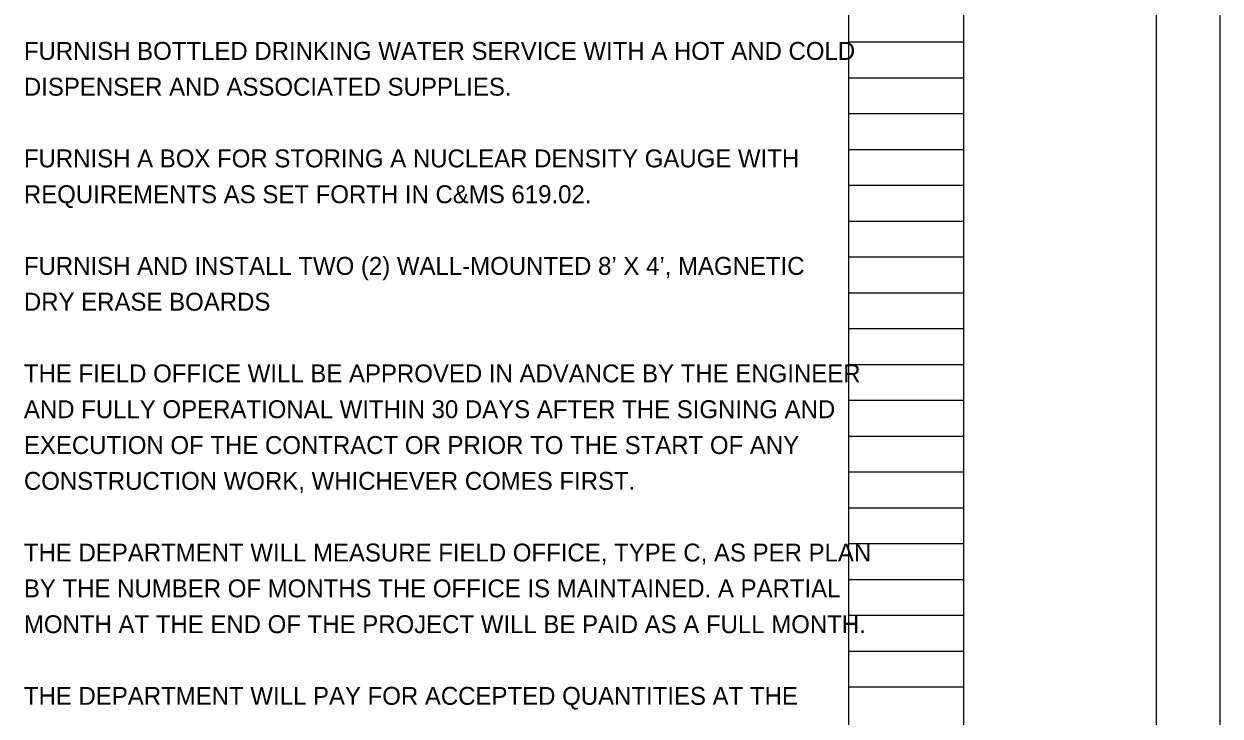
# Model space of a CAD drawing. Extents: x 0 to 74, y -27.6 to 51.8.
# Drawn here: x 24.66 to 34, y 5.51 to 10.92 of the extents above; entities that cross this region are included whole.
import ezdxf

# ---------------------------------------------------------------- set-up
doc = ezdxf.new("R2010")
doc.units = 0
for name, color, linetype in [('Level 1', 7, 'Continuous'), ('Level 2', 7, 'Continuous'), ('Level 3', 7, 'Continuous'), ('Level 4', 7, 'Continuous')]:
    doc.layers.add(name, color=color, linetype=linetype)

msp = doc.modelspace()

# ---------------------------------------------------------------- linework, layer by layer
at = {"layer": 'Level 1'}
msp.add_lwpolyline([(0, 0), (34, 0), (34, 22), (0, 22)], close=True, dxfattribs=at)
at = {"layer": 'Level 2'}
msp.add_line((32, 0.5), (32, 21.5), dxfattribs=at)
msp.add_lwpolyline([(1.5, 21.5), (33.5, 21.5), (33.5, 0.5), (1.5, 0.5)], close=True, dxfattribs=at)
at = {"layer": 'Level 3'}
for p, q in [((31.1, 0.98), (31.1, 21.14)), ((32, 0.98), (32, 21.14)), ((31.1, 10.78), (32, 10.78)), ((31.1, 10.5), (32, 10.5)), ((31.1, 10.22), (32, 10.22)), ((31.1, 9.94), (32, 9.94)), ((31.1, 9.66), (32, 9.66)), ((31.1, 9.38), (32, 9.38)), ((31.1, 9.1), (32, 9.1)), ((31.1, 8.82), (32, 8.82)), ((31.1, 8.54), (32, 8.54)), ((31.1, 8.26), (32, 8.26)), ((31.1, 7.98), (32, 7.98)), ((31.1, 7.7), (32, 7.7)), ((31.1, 7.42), (32, 7.42)), ((31.1, 7.14), (32, 7.14)), ((31.1, 6.86), (32, 6.86)), ((31.1, 6.58), (32, 6.58)), ((31.1, 6.3), (32, 6.3)), ((31.1, 6.02), (32, 6.02)), ((31.1, 5.74), (32, 5.74))]:
    msp.add_line(p, q, dxfattribs=at)

# ---------------------------------------------------------------- texts
at = {"layer": 'Level 4'}
for s, p in [('FURNISH BOTTLED DRINKING WATER SERVICE WITH A HOT AND COLD ', (24.66, 10.64)), ('DISPENSER AND ASSOCIATED SUPPLIES.', (24.66, 10.36)), ('FURNISH A BOX FOR STORING A NUCLEAR DENSITY GAUGE WITH ', (24.66, 9.8)), ('REQUIREMENTS AS SET FORTH IN C&MS 619.02.', (24.66, 9.52)), ('FURNISH AND INSTALL TWO (2) WALL-MOUNTED 8’ X 4’, MAGNETIC ', (24.66, 8.96)), ('DRY ERASE BOARDS', (24.66, 8.68)), ('THE FIELD OFFICE WILL BE APPROVED IN ADVANCE BY THE ENGINEER ', (24.66, 8.12)), ('AND FULLY OPERATIONAL WITHIN 30 DAYS AFTER THE SIGNING AND ', (24.66, 7.84)), ('EXECUTION OF THE CONTRACT OR PRIOR TO THE START OF ANY ', (24.66, 7.56)), ('CONSTRUCTION WORK, WHICHEVER COMES FIRST.', (24.66, 7.28)), ('THE DEPARTMENT WILL MEASURE FIELD OFFICE, TYPE C, AS PER PLAN ', (24.66, 6.72)), ('BY THE NUMBER OF MONTHS THE OFFICE IS MAINTAINED. A PARTIAL ', (24.66, 6.44)), ('MONTH AT THE END OF THE PROJECT WILL BE PAID AS A FULL MONTH.', (24.66, 6.16)), ('THE DEPARTMENT WILL PAY FOR ACCEPTED QUANTITIES AT THE ', (24.66, 5.6))]:
    msp.add_text(s, height=0.14, dxfattribs=at).set_placement(p)

doc.saveas('drawing.dxf')
